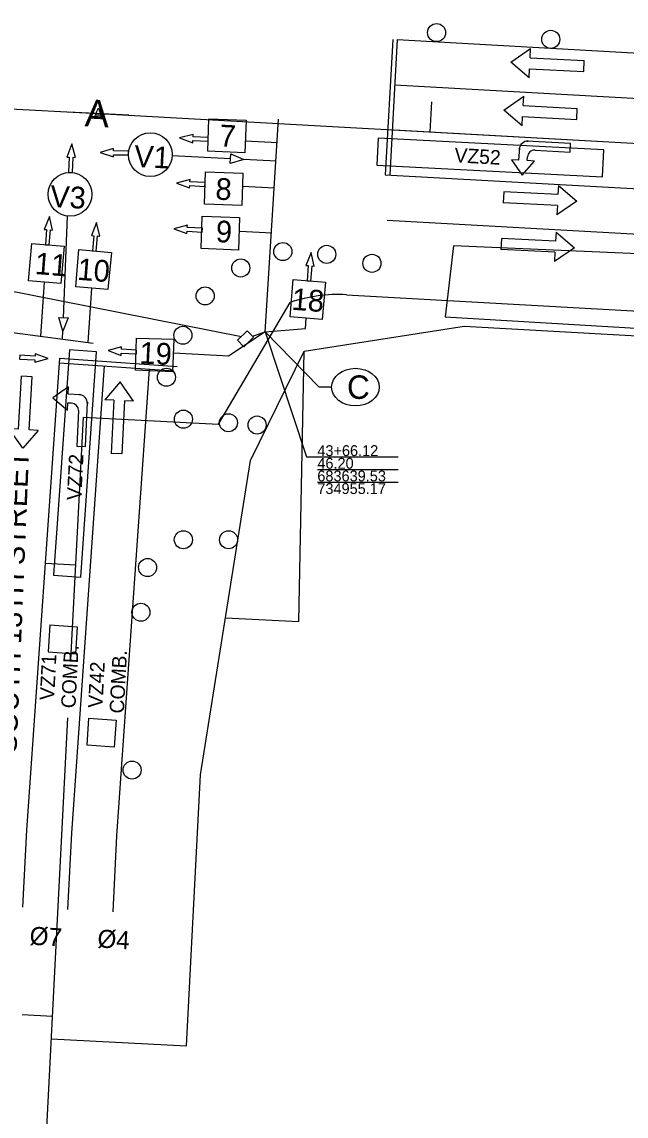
# Model space of a CAD drawing. Extents: x 679444 to 687671, y 733868 to 736107.
# Drawn here: x 683585.7 to 683719.4, y 734781.6 to 735023.8 of the extents above; entities that cross this region are included whole.
import ezdxf

# ---------------------------------------------------------------- set-up
doc = ezdxf.new("R2010")
doc.units = 0
for name, color, linetype in [('$', 7, 'Continuous'), ('090338 Base_ROW 3 - R_Horz Alg', 7, 'Continuous'), ('Clipping Boundary', 7, 'Continuous'), ('MOT Stage 1', 7, 'Continuous'), ('MOT Stage 1 Lanes', 7, 'Continuous'), ('R_Horz Alg', 7, 'Continuous'), ('R_Horz Alg Annot', 7, 'Continuous'), ('R_Horz Alg Station', 7, 'Continuous'), ('RW-EX', 7, 'Continuous'), ('RW-PR', 7, 'Continuous'), ('SIGNAL-EX', 7, 'Continuous'), ('SIGNAL-PLAN VIEW LABLES', 7, 'Continuous'), ('TITEXT', 7, 'Continuous'), ('Video-Zones-pr', 7, 'Continuous')]:
    doc.layers.add(name, color=color, linetype=linetype)

# ---------------------------------------------------------------- blocks, each defined once
blk = doc.blocks.new('BAREL_1627')
at = {"layer": 'MOT Stage 1'}
blk.add_circle((0, 0.01), 2.88, dxfattribs=at)
blk = doc.blocks.new('SARROW_187')
at = {"layer": 'MOT Stage 1'}
for p, q in [((0, 0), (-6, 0)), ((0, -29.42), (0, 0)), ((-6, -29.42), (-6, 0)), ((-6, -29.42), (-11, -29.42)), ((-3, -39.81), (-11, -29.42)), ((5, -29.42), (-3, -39.81)), ((5, -29.42), (0, -29.42))]:
    blk.add_line(p, q, dxfattribs=at)
blk = doc.blocks.new('SARROW_188')
at = {"layer": 'MOT Stage 1'}
for p, q in [((0, 0), (-6, 0)), ((0, -29.42), (0, 0)), ((-6, -29.42), (-6, 0)), ((-6, -29.42), (-11, -29.42)), ((-3, -39.81), (-11, -29.42)), ((5, -29.42), (-3, -39.81)), ((5, -29.42), (0, -29.42))]:
    blk.add_line(p, q, dxfattribs=at)
blk = doc.blocks.new('SARROW_189')
at = {"layer": 'MOT Stage 1'}
for p, q in [((0, 0), (-6, 0)), ((0, -29.42), (0, 0)), ((-6, -29.42), (-6, 0)), ((-6, -29.42), (-11, -29.42)), ((-3, -39.81), (-11, -29.42)), ((5, -29.42), (-3, -39.81)), ((5, -29.42), (0, -29.42))]:
    blk.add_line(p, q, dxfattribs=at)
blk = doc.blocks.new('SARROW_190')
at = {"layer": 'MOT Stage 1'}
for p, q in [((-6, -29.42), (-6, 0)), ((0, 0), (-6, 0)), ((0, -29.42), (0, 0)), ((-6, -29.42), (-11, -29.42)), ((-3, -39.81), (-11, -29.42)), ((5, -29.42), (-3, -39.81)), ((5, -29.42), (0, -29.42))]:
    blk.add_line(p, q, dxfattribs=at)
blk = doc.blocks.new('BAREL_1681')
at = {"layer": 'MOT Stage 1'}
blk.add_circle((0, 0.01), 2.88, dxfattribs=at)
blk = doc.blocks.new('SARROW_203')
at = {"layer": 'MOT Stage 1'}
for p, q in [((-6, -29.42), (-6, 0)), ((0, 0), (-6, 0)), ((0, -29.42), (0, 0)), ((-6, -29.42), (-11, -29.42)), ((-3, -39.81), (-11, -29.42)), ((5, -29.42), (-3, -39.81)), ((5, -29.42), (0, -29.42))]:
    blk.add_line(p, q, dxfattribs=at)
blk = doc.blocks.new('SARROW_204')
at = {"layer": 'MOT Stage 1'}
for p, q in [((-6, -29.42), (-6, 0)), ((0, 0), (-6, 0)), ((0, -29.42), (0, 0)), ((-6, -29.42), (-11, -29.42)), ((-3, -39.81), (-11, -29.42)), ((5, -29.42), (-3, -39.81)), ((5, -29.42), (0, -29.42))]:
    blk.add_line(p, q, dxfattribs=at)
blk = doc.blocks.new('BAREL_1729')
at = {"layer": 'MOT Stage 1'}
blk.add_circle((0, 0.01), 2.88, dxfattribs=at)
blk = doc.blocks.new('BAREL_1730')
at = {"layer": 'MOT Stage 1'}
blk.add_circle((0, 0.01), 2.88, dxfattribs=at)
blk = doc.blocks.new('BAREL_1731')
at = {"layer": 'MOT Stage 1'}
blk.add_circle((0, 0.01), 2.88, dxfattribs=at)
blk = doc.blocks.new('BAREL_1732')
at = {"layer": 'MOT Stage 1'}
blk.add_circle((0, 0.01), 2.88, dxfattribs=at)
blk = doc.blocks.new('BAREL_1733')
at = {"layer": 'MOT Stage 1'}
blk.add_circle((0, 0.01), 2.88, dxfattribs=at)
blk = doc.blocks.new('BAREL_1734')
at = {"layer": 'MOT Stage 1'}
blk.add_circle((0, 0.01), 2.88, dxfattribs=at)
blk = doc.blocks.new('BAREL_1735')
at = {"layer": 'MOT Stage 1'}
blk.add_circle((0, 0.01), 2.88, dxfattribs=at)
blk = doc.blocks.new('BAREL_1736')
at = {"layer": 'MOT Stage 1'}
blk.add_circle((0, 0.01), 2.88, dxfattribs=at)
blk = doc.blocks.new('BAREL_1737')
at = {"layer": 'MOT Stage 1'}
blk.add_circle((0, 0.01), 2.88, dxfattribs=at)
blk = doc.blocks.new('BAREL_1738')
at = {"layer": 'MOT Stage 1'}
blk.add_circle((0, 0.01), 2.88, dxfattribs=at)
blk = doc.blocks.new('BAREL_1739')
at = {"layer": 'MOT Stage 1'}
blk.add_circle((0, 0.01), 2.88, dxfattribs=at)
blk = doc.blocks.new('BAREL_1740')
at = {"layer": 'MOT Stage 1'}
blk.add_circle((0, 0.01), 2.88, dxfattribs=at)
blk = doc.blocks.new('BAREL_1741')
at = {"layer": 'MOT Stage 1'}
blk.add_circle((0, 0.01), 2.88, dxfattribs=at)
blk = doc.blocks.new('BAREL_1742')
at = {"layer": 'MOT Stage 1'}
blk.add_circle((0, 0.01), 2.88, dxfattribs=at)
blk = doc.blocks.new('BAREL_1743')
at = {"layer": 'MOT Stage 1'}
blk.add_circle((0, 0.01), 2.88, dxfattribs=at)

msp = doc.modelspace()

# ---------------------------------------------------------------- linework, layer by layer
at = {"layer": 'Clipping Boundary'}
msp.add_lwpolyline([(683681.22, 734974.2), (683679.4, 734958.5), (684555.95, 734906.39), (684558.45, 734936.24)], close=True, dxfattribs=at)
at = {"layer": 'MOT Stage 1'}
for points in [[(683695.76, 734995.56), (683695.78, 734995.88), (683695.63, 734993.15), (683694.05, 734993.23), (683696.41, 734989.81), (683699.12, 734992.97), (683697.54, 734993.05), (683697.58, 734993.87)], [(683707.14, 734996.87), (683697.45, 734997.38), (683697.77, 734997.36)], [(683699.25, 734995.38), (683707.03, 734994.96), (683707.14, 734996.87)], [(683598.36, 734941.28), (683598.68, 734941.27), (683595.93, 734941.39), (683596, 734942.99), (683592.57, 734940.57), (683595.77, 734937.87), (683595.84, 734939.47), (683596.68, 734939.43)], [(683598.21, 734937.76), (683597.86, 734929.91), (683599.78, 734929.83)], [(683599.78, 734929.83), (683600.21, 734939.6), (683600.19, 734939.28)]]:
    msp.add_lwpolyline(points, dxfattribs=at)
for centre, radius, start, end in [((683697.66, 734995.46), 1.9, 86.9687, 176.9687), ((683699.17, 734993.79), 1.59, 86.9687, 176.9687), ((683598.27, 734939.36), 1.92, 357.5178, 87.5178), ((683596.61, 734937.83), 1.6, 357.5178, 87.5178)]:
    msp.add_arc(centre, radius, start, end, dxfattribs=at)
at = {"layer": 'MOT Stage 1 Lanes'}
for p, q in [((683667.78, 735019.89), (683666.1, 734989.94)), ((683668.77, 735019.83), (683667.1, 734989.88)), ((683668.77, 735019.83), (683776.9, 735013.79)), ((683668.22, 735009.85), (683732.17, 735006.27)), ((683666.66, 734999.92), (683775.78, 734993.82)), ((683666.1, 734989.94), (683775.22, 734983.83)), ((683666.54, 734979.9), (683774.66, 734973.85)), ((683585.91, 734827.88), (683586.78, 734844.88))]:
    msp.add_line(p, q, dxfattribs=at)
for points in [[(683586.78, 734844.88), (683594.07, 734949.32), (683620.04, 734947.51)], [(683594, 734948.32), (683619.33, 734946.56)], [(683595.89, 734827.37), (683596.76, 734844.27), (683603.97, 734947.63)], [(683605.88, 734826.85), (683606.74, 734843.67), (683613.95, 734946.93)]]:
    msp.add_lwpolyline(points, dxfattribs=at)
at = {"layer": 'R_Horz Alg Annot'}
for p, q in [((683651.08, 734927.49), (683668.93, 734927.49)), ((683651.08, 734924.69), (683668.93, 734924.69)), ((683651.08, 734921.89), (683668.93, 734921.89))]:
    msp.add_line(p, q, dxfattribs=at)
msp.add_lwpolyline([(683639.53, 734955.17), (683648.68, 734927.49), (683651.08, 734927.49)], dxfattribs=at)
at = {"layer": 'R_Horz Alg Station'}
for p, q in [((683438.62, 735011.92), (683602.68, 735003.5)), ((683602.68, 735003.5), (683955.13, 734983.79))]:
    msp.add_line(p, q, dxfattribs=at)
for points in [[(683676.31, 735006.06), (683675.94, 734999.4)], [(683596.02, 735003.84), (683609.34, 735003.16)], [(683590.9, 734903.97), (683597.56, 734903.63)], [(683585.77, 734804.1), (683592.43, 734803.76)]]:
    msp.add_lwpolyline(points, dxfattribs=at)
at = {"layer": 'RW-EX'}
for p, q in [((683629.19, 734934.75), (683645.1, 734961.68)), ((683657.53, 734963.37), (683733.41, 734959.13)), ((683599.23, 734936.29), (683596.47, 734882.59)), ((683599.23, 734936.29), (683629.19, 734934.75)), ((683595.82, 734869.77), (683567.97, 734327.38))]:
    msp.add_line(p, q, dxfattribs=at)
msp.add_arc((683655.68, 734930.43), 33, 86.7989, 108.7102, dxfattribs=at)
at = {"layer": 'RW-PR'}
for p, q in [((683646.98, 734891.08), (683648.18, 734950.88)), ((683630.75, 734891.91), (683646.98, 734891.08))]:
    msp.add_line(p, q, dxfattribs=at)
for points in [[(683648.18, 734950.88), (683683.55, 734956.41), (683823.33, 734948.59), (683952.62, 734938.86), (684206.41, 734924.66)], [(683592.17, 734798.77), (683622.13, 734797.23), (683625.21, 734857.15), (683636.29, 734926.68), (683648.18, 734950.88)]]:
    msp.add_lwpolyline(points, dxfattribs=at)
at = {"layer": 'SIGNAL-EX'}
for p, q in [((683639.53, 734955.17), (683642.46, 735002.24)), ((683564.03, 734957.59), (683601.5, 734952.7))]:
    msp.add_line(p, q, dxfattribs=at)
for points in [[(683554.4, 734969.91), (683634.28, 734954.17)], [(683636.75, 734954.19), (683639.53, 734955.17)]]:
    msp.add_lwpolyline(points, dxfattribs=at)
msp.add_lwpolyline([(683633.41, 734953.33), (683635.56, 734955.41), (683636.95, 734953.98), (683634.8, 734951.89)], close=True, dxfattribs=at)
at = {"layer": 'SIGNAL-PLAN VIEW LABLES'}
for points in [[(683626.81, 734995.16), (683627.06, 735002.29), (683635.31, 735002), (683635.06, 734994.8)], [(683634.84, 734993.33), (683631.82, 734992.45), (683631.95, 734994.53)], [(683626.1, 734983.45), (683626.35, 734990.58), (683634.6, 734990.3), (683634.35, 734983.1)], [(683625.37, 734973.63), (683625.62, 734980.76), (683633.88, 734980.47), (683633.63, 734973.27)], [(683594.29, 734965.88), (683587.18, 734966.49), (683587.88, 734974.72), (683595.06, 734974.1)], [(683604.72, 734964.52), (683597.61, 734965.13), (683598.32, 734973.36), (683605.49, 734972.74)], [(683652.14, 734957.9), (683645.03, 734958.51), (683645.74, 734966.74), (683652.91, 734966.13)], [(683594.76, 734955.33), (683593.84, 734958.34), (683595.92, 734958.24)], [(683610.8, 734946.68), (683611.05, 734953.81), (683619.31, 734953.53), (683619.06, 734946.33)]]:
    msp.add_lwpolyline(points, close=True, dxfattribs=at)
for points in [[(683623.57, 734998.34), (683623.59, 734998.85), (683620.6, 734998.08), (683623.5, 734997), (683623.52, 734997.5), (683626.88, 734997.33), (683626.92, 734998.17), (683623.57, 734998.34)], [(683626.92, 734998.17), (683623.57, 734998.34), (683623.59, 734998.85), (683620.6, 734998.08), (683623.5, 734997), (683623.52, 734997.5), (683626.88, 734997.33)], [(683597.01, 734993.79), (683597.52, 734993.76), (683596.73, 734996.75), (683595.67, 734993.85), (683596.17, 734993.83), (683596.02, 734990.47), (683596.86, 734990.43), (683597.01, 734993.79)], [(683596.86, 734990.43), (683597.01, 734993.79), (683597.52, 734993.76), (683596.73, 734996.75), (683595.67, 734993.85), (683596.17, 734993.83), (683596.02, 734990.47)], [(683605.96, 734995.2), (683605.97, 734995.71), (683603, 734994.84), (683605.93, 734993.86), (683605.94, 734994.36), (683609.3, 734994.3), (683609.32, 734995.14), (683605.96, 734995.2)], [(683609.32, 734995.14), (683605.96, 734995.2), (683605.97, 734995.71), (683603, 734994.84), (683605.93, 734993.86), (683605.94, 734994.36), (683609.3, 734994.3)], [(683642.24, 734996.96), (683635.13, 734997.33)], [(683631.89, 734993.48), (683618.96, 734994.13)], [(683641.99, 734992.97), (683634.84, 734993.33)], [(683622.89, 734988.36), (683622.92, 734988.87), (683619.93, 734988.1), (683622.82, 734987.02), (683622.85, 734987.53), (683626.2, 734987.35), (683626.25, 734988.19), (683622.89, 734988.36)], [(683626.25, 734988.19), (683622.89, 734988.36), (683622.92, 734988.87), (683619.93, 734988.1), (683622.82, 734987.02), (683622.85, 734987.53), (683626.2, 734987.35)], [(683641.62, 734986.98), (683634.51, 734987.35)], [(683591.99, 734977.74), (683592.49, 734977.7), (683591.8, 734980.72), (683590.65, 734977.85), (683591.15, 734977.81), (683590.89, 734974.46), (683591.73, 734974.39), (683591.99, 734977.74)], [(683591.73, 734974.39), (683591.99, 734977.74), (683592.49, 734977.7), (683591.8, 734980.72), (683590.65, 734977.85), (683591.15, 734977.81), (683590.89, 734974.46)], [(683594.91, 734958.29), (683595.8, 734980.79)], [(683602.42, 734976.38), (683602.92, 734976.34), (683602.23, 734979.36), (683601.08, 734976.49), (683601.58, 734976.45), (683601.32, 734973.1), (683602.16, 734973.03), (683602.42, 734976.38)], [(683602.16, 734973.03), (683602.42, 734976.38), (683602.92, 734976.34), (683602.23, 734979.36), (683601.08, 734976.49), (683601.58, 734976.45), (683601.32, 734973.1)], [(683622.3, 734978.26), (683622.33, 734978.77), (683619.33, 734978), (683622.23, 734976.92), (683622.26, 734977.43), (683625.61, 734977.25), (683625.66, 734978.09), (683622.3, 734978.26)], [(683625.66, 734978.09), (683622.3, 734978.26), (683622.33, 734978.77), (683619.33, 734978), (683622.23, 734976.92), (683622.26, 734977.43), (683625.61, 734977.25)], [(683641, 734977), (683633.89, 734977.37)], [(683649.9, 734969.76), (683650.41, 734969.72), (683649.71, 734972.73), (683648.56, 734969.86), (683649.07, 734969.82), (683648.81, 734966.47), (683649.64, 734966.41), (683649.9, 734969.76)], [(683649.64, 734966.41), (683649.9, 734969.76), (683650.41, 734969.72), (683649.71, 734972.73), (683648.56, 734969.86), (683649.07, 734969.82), (683648.81, 734966.47)], [(683589.9, 734954.21), (683590.73, 734966.18)], [(683600.33, 734952.85), (683601.16, 734964.82)], [(683639.53, 734955.17), (683648.43, 734955.94), (683648.59, 734958.21)], [(683594.68, 734953.59), (683594.76, 734955.33)], [(683639.53, 734955.17), (683631.45, 734949.8), (683619.32, 734950.42)], [(683639.53, 734955.17), (683651.38, 734942.98), (683654.24, 734942.98)], [(683588.55, 734948.98), (683588.53, 734948.48), (683591.52, 734949.25), (683588.62, 734950.33), (683588.6, 734949.82), (683585.24, 734950), (683585.2, 734949.16), (683588.55, 734948.98)], [(683585.2, 734949.16), (683588.55, 734948.98), (683588.53, 734948.48), (683591.52, 734949.25), (683588.62, 734950.33), (683588.6, 734949.82), (683585.24, 734950)], [(683607.73, 734951.32), (683607.76, 734951.82), (683604.77, 734951.05), (683607.66, 734949.97), (683607.69, 734950.48), (683611.05, 734950.31), (683611.09, 734951.14), (683607.73, 734951.32)], [(683611.09, 734951.14), (683607.73, 734951.32), (683607.76, 734951.82), (683604.77, 734951.05), (683607.66, 734949.97), (683607.69, 734950.48), (683611.05, 734950.31)]]:
    msp.add_lwpolyline(points, dxfattribs=at)
for centre in [(683614.12, 734994.38), (683596.33, 734985.61)]:
    msp.add_circle(centre, 4.85, dxfattribs=at)
msp.add_ellipse((683659.51, 734942.94), major_axis=(-5.27, 0), ratio=0.790685, dxfattribs=at)
at = {"layer": 'Video-Zones-pr'}
for points in [[(683664.23, 734992.05), (683714.16, 734989.48), (683714.47, 734995.48), (683664.54, 734998.04)], [(683596.2, 734951.18), (683592.72, 734901.32), (683598.71, 734900.86), (683602.19, 734950.76)]]:
    msp.add_lwpolyline(points, close=True, dxfattribs=at)
for points in [[(683591.91, 734890.33), (683591.54, 734884.34)], [(683591.91, 734890.33), (683597.9, 734889.91)], [(683597.9, 734889.91), (683597.52, 734883.92)], [(683591.54, 734884.34), (683597.52, 734883.92)], [(683600.54, 734869.68), (683606.52, 734869.26), (683606.11, 734863.28), (683600.12, 734863.69), (683600.54, 734869.68)]]:
    msp.add_lwpolyline(points, dxfattribs=at)

# ---------------------------------------------------------------- block references
at = {"layer": 'MOT Stage 1'}
for name, p, xscale, yscale, rotation in [('BAREL_1627', (683677.47, 735021.38), 0.6945420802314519, 0.694542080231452, 102.17652807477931), ('BAREL_1681', (683702.75, 735019.89), 0.6945420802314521, 0.6945420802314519, 87.04179557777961), ('SARROW_188', (683710.02, 735012.75), 0.40758735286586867, 0.4075873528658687, -93.0312882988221), ('SARROW_187', (683708.48, 735002.17), 0.40758735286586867, 0.4075873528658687, -93.0312882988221), ('SARROW_189', (683692.35, 734986.18), 0.40758735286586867, 0.4075873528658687, 86.96871170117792), ('SARROW_190', (683691.82, 734975.85), 0.40758735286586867, 0.4075873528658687, 86.96871170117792), ('BAREL_1731', (683643.45, 734972.94), 0.6945420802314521, 0.6945420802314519, 87.04179557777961), ('BAREL_1730', (683653.17, 734972.32), 0.6945420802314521, 0.6945420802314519, 87.04179557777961), ('BAREL_1732', (683634.14, 734969.3), 0.6945420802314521, 0.6945420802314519, 87.04179557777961), ('BAREL_1729', (683663.17, 734970.33), 0.6945420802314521, 0.6945420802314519, 87.04179557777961), ('BAREL_1733', (683626.26, 734963.13), 0.6945420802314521, 0.6945420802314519, 87.04179557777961), ('BAREL_1734', (683621.33, 734954.43), 0.6945420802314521, 0.6945420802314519, 87.04179557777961), ('BAREL_1735', (683617.68, 734945.12), 0.6945420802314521, 0.6945420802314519, 87.04179557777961), ('SARROW_203', (683587.98, 734945.23), 0.4, 0.39999999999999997, -3.300150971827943), ('SARROW_204', (683607.84, 734928.16), 0.40000000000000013, -0.4000000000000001, -2.7707692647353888), ('BAREL_1736', (683621.44, 734935.85), 0.6945420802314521, 0.6945420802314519, 87.04179557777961), ('BAREL_1737', (683631.4, 734935.05), 0.6945420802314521, 0.6945420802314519, 87.04179557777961), ('BAREL_1738', (683637.76, 734934.56), 0.6945420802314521, 0.6945420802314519, 87.04179557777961), ('BAREL_1740', (683621.43, 734909.16), 0.6945420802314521, 0.6945420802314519, 87.04179557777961), ('BAREL_1739', (683631.43, 734909.16), 0.6945420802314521, 0.6945420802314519, 87.04179557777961), ('BAREL_1741', (683613.52, 734903.03), 0.6945420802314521, 0.6945420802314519, 87.04179557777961), ('BAREL_1742', (683612.03, 734893.14), 0.6945420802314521, 0.6945420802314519, 87.04179557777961), ('BAREL_1743', (683610.09, 734858.2), 0.6945420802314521, 0.6945420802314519, 87.04179557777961)]:
    msp.add_blockref(name, p, dxfattribs=dict(at, xscale=xscale, yscale=yscale, rotation=rotation))

# ---------------------------------------------------------------- texts
at = {"layer": '$'}
for s, height, rotation, p in [('VZ52', 3.2, 356.7989, (683681.35, 734992.7)), ('SOUTH 13TH STREET', 4.8, 87.5995, (683584.49, 734861.81)), ('VZ72', 3.2, 87.0608, (683598.82, 734917.83)), ('COMB.', 3.2, 87.0608, (683597.54, 734871.82)), ('COMB.', 3.2, 87.0608, (683608.26, 734870.67)), ('VZ71', 3.2, 87.0608, (683592.82, 734873.59)), ('VZ42', 3.2, 87.0608, (683603.52, 734871.89))]:
    msp.add_text(s, height=height, rotation=rotation, dxfattribs=at).set_placement(p)
at = {"layer": '090338 Base_ROW 3 - R_Horz Alg'}
msp.add_text('A', height=2.4, rotation=356.9312, dxfattribs=at).set_placement((683601.43, 735002.37))
at = {"layer": 'R_Horz Alg'}
msp.add_text('A', height=6, rotation=356.9312, dxfattribs=at).set_placement((683599.53, 735000.66))
at = {"layer": 'R_Horz Alg Annot'}
for s, p in [('43+66.12', (683651.08, 734927.69)), ('46.20', (683651.08, 734924.89)), ('683639.53', (683651.08, 734922.09)), ('734955.17', (683651.08, 734919.29))]:
    msp.add_text(s, height=2.4, dxfattribs=at).set_placement(p)
at = {"layer": 'SIGNAL-PLAN VIEW LABLES'}
for s, rotation, p in [('7', 357.0414, (683629.35, 734996.24)), ('V1', 357.0414, (683610.45, 734991.69)), ('8', 357.0414, (683628.44, 734984.46)), ('V3', 357.0414, (683591.87, 734982.8)), ('9', 357.0414, (683628.52, 734975.05)), ('11', 355.5482, (683588.44, 734967.98)), ('10', 355.5482, (683597.85, 734966.7)), ('18', 355.5482, (683645.27, 734960.08)), ('19', 357.0414, (683611.62, 734948.19))]:
    msp.add_text(s, height=4.8, rotation=rotation, dxfattribs=at).set_placement(p)
msp.add_text('C', height=5.2, dxfattribs=at).set_placement((683657.65, 734940.34))
at = {"layer": 'TITEXT'}
for s, p in [('%%C7', (683587.31, 734819.62)), ('%%C4', (683602.32, 734818.99))]:
    msp.add_text(s, height=4, rotation=356.2723, dxfattribs=at).set_placement(p)

doc.saveas('drawing.dxf')
